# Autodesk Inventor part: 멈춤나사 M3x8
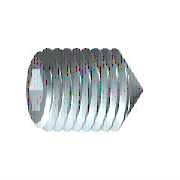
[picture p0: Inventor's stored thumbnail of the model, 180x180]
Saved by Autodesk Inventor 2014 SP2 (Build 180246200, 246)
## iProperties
Created: 2012-02
Part Number: 멈춤나사 M3x8
Material: 강철, 연강
Description: 6각 소켓 머리 없는 멈춤 나사
Document SubType Name: Modeling
Standard: KS B 1028
Designer: mduedu
Standards Organization: KS
Language: ko-KR
Size Designation: 원추점 M3x8
Categories: <MemberInstance><Categories><Category DisplayName="조임쇠" InternalName="e4da775c-781d-43d5-af7c-5136215cf5a6" Mnemonic="FSTN"><Category DisplayName="볼트" InternalN
Density: 7.86 g/cm^3
Mass: 0.360339 g
Surface Area: 0.888172 cm^2
Volume: 0.0458447 cm^3
Appearance: 강철
IsCustomPart: 1
Author: mduedu
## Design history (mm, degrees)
sketch "스케치1"
  geometry: L1 (0, 0)-(5.5, 0); L2 (8, 0.866)-(8, 1.5); L3 (8, 1.5)-(0, 1.5); L4 (8, 0.866)-(6, 0.866); L5 (6, 0.866)-(5.5, 0); L6 (0, -0.3)-(0, 1.8) reference; L7 (0, 1.5)-(0, 0)
  constraints: 13 end point, 3 parallel, 1 collinear, 1 perpendicular, 1 point on line
  dimensions: "d0" = 2 distance of L2.start L4.end (= INTI); "d1" = 60 deg angle of L5 L1; "d2" = 3 diameter of L3 L1 (= NND); "d3" = 1.73205 diameter of L4 L1 (= 1.1547 x SW); "d5" = 8 distance from line of L2 L3.end (= NLG)
revolve "본체" sketch "스케치1" stored, may be unused: angle "d6" = 90 deg
sketch "스케치2"
  geometry: L1 (-0.433, 0.75)-(0.433, 0.75); L2 (0.433, 0.75)-(0.866, 0); L3 (0.866, 0)-(0.433, -0.75); L4 (0.433, -0.75)-(-0.433, -0.75); L5 (-0.433, -0.75)-(-0.866, 0); L6 (-0.866, 0)-(-0.433, 0.75); 3 further points
  constraints: 12 end point, 1 coincident, 1 horizontal, 13 other
extrude "슬롯" join sketch "스케치2" taper "d7" = 0 deg; stored distance "d21" = 10
workaxis "Work Axis1"
workplane "Work Plane1"
sketch "스케치5"
  geometry: L1 (-4, -0.15)-(-2.65, -1.5) reference; L2 (-4, 0.15)-(-2.65, 1.5) reference; L3 (-2.65, 1.5)-(-4.15, 0); L4 (-2.65, -1.5)-(-4.15, 0); 1 further point
  constraints: 4 end point, 1 horizontal alignment, 1 perpendicular
node "작업점1"
body "Solid1"
feature "스레드" dims "d12" = 8 (= NLG), "d13" = 0
chamfer "모따기1" distance "d8" = 1.35 (computed from NND, SPD, FAWI); stored, may be unused: angle "d9" = 45 deg (= FAWI), second distance "d34" = 1.35 (computed from NND, SPD, FAWI)
chamfer "모따기2" distance "d10" = 0.30673 (= -0.5 x GD1 + 0.5 x NND); stored, may be unused: angle "d11" = 45 deg (= FAWI), second distance "d35" = 0.30673 (= -0.5 x GD1 + 0.5 x NND)
other parameters: "NND" = 3 [user parameter; used in 5 equation terms], "NLG" = 8 [user parameter; used in 2 equation terms], "INTI" = 2 [user parameter; used in 1 equation term], "FAWI" = 45 deg [user parameter; used in 4 equation terms], "SW" = 1.5 [user parameter; used in 2 equation terms], "GD1" = 2.38655 (= THREADDIA - 1.2269 x PTC) [user parameter; used in 2 equation terms], "d4" = 0, "FAWI1" = 45 deg [user parameter], "SPD" = 0.3 [user parameter; used in 2 equation terms], "d36" = 0, "d37" = 0, "GUL" = 0.30673 (= 0.61345 x PTC) [user parameter], "TOA" = 30 deg [user parameter], "THREADDIA" = 3 [user parameter; used in 1 equation term], "PTC" = 0.5 [user parameter; used in 4 equation terms], "GAL" = 0.30673 (= 0.61345 x PTC) [user parameter], "E0" = 1.7325 (= 1.155 x SW) [user parameter]
